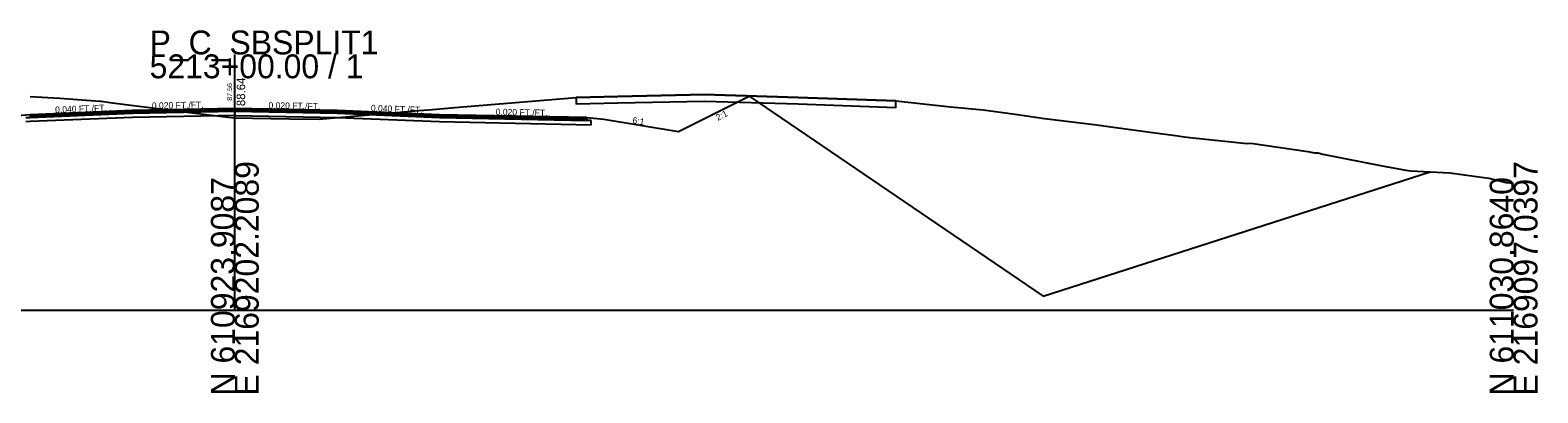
# Model space of a CAD drawing. Extents: x -26 to 1303, y -3010 to 12033.
# Drawn here: x 1126 to 1302.8, y 8490.3 to 8532.8 of the extents above; entities that cross this region are included whole.
import ezdxf

# ---------------------------------------------------------------- set-up
doc = ezdxf.new("R2010")
doc.units = 0
for name, color, linetype in [('RD_GPK_XS_Cell', 7, 'Continuous'), ('RD_Sketch10', 7, 'Continuous'), ('RD_XS_Base', 7, 'Continuous'), ('RD_XS_ExGround', 7, 'Continuous'), ('RD_XS_ExPaveRet', 7, 'Continuous'), ('RD_XS_Greenside', 7, 'Continuous'), ('RD_XS_Pave', 7, 'Continuous'), ('RD_XS_PaveOvlay_CP', 7, 'Continuous'), ('RD_XS_TieSlope', 7, 'Continuous'), ('RD_XS_TX_Elev_EX', 7, 'Continuous'), ('RD_XS_TX_Elev_PR', 7, 'Continuous'), ('RD_XS_TX_Slope', 7, 'Continuous')]:
    doc.layers.add(name, color=color, linetype=linetype)

msp = doc.modelspace()

# ---------------------------------------------------------------- linework, layer by layer
at = {"layer": 'RD_GPK_XS_Cell'}
for p, q in [((1150, 8500), (1150, 8530)), ((1000, 8500), (1150, 8500)), ((1150, 8500), (1300, 8500))]:
    msp.add_line(p, q, dxfattribs=at)
at = {"layer": 'RD_Sketch10'}
msp.add_lwpolyline([(1210.33, 8525.12), (1244.82, 8501.65), (1290.21, 8516.23)], dxfattribs=at)
at = {"layer": 'RD_XS_Base'}
for p, q in [((1125.5, 8522.59), (1126, 8522.61)), ((1126, 8522.61), (1138, 8523.09)), ((1126, 8522.61), (1126, 8522.61)), ((1138, 8522.59), (1126, 8522.11)), ((1136, 8523.01), (1136, 8523.01)), ((1136, 8522.51), (1136, 8522.51)), ((1138, 8523.09), (1150, 8523.33)), ((1150, 8522.83), (1138, 8522.59)), ((1150, 8523.33), (1150, 8523.49)), ((1150, 8523.49), (1150, 8522.83)), ((1150, 8523.33), (1150, 8522.83)), ((1150, 8523.33), (1150, 8523.33)), ((1162, 8523.09), (1150, 8523.33)), ((1150, 8523.33), (1150, 8523.33)), ((1150, 8522.83), (1150, 8522.83)), ((1150, 8522.83), (1150, 8522.83)), ((1150, 8522.83), (1162, 8522.59)), ((1174, 8522.61), (1162, 8523.09)), ((1162, 8523.09), (1162, 8523.09)), ((1162, 8522.59), (1162, 8522.59)), ((1162, 8522.59), (1174, 8522.11)), ((1191.3, 8522.26), (1174, 8522.61)), ((1174, 8522.61), (1174, 8522.61)), ((1126, 8522.11), (1125.5, 8522.09)), ((1126, 8522.11), (1126, 8522.11)), ((1174, 8522.11), (1174, 8522.11)), ((1174, 8522.11), (1191.8, 8521.75)), ((1191.8, 8522.25), (1191.3, 8522.26)), ((1191.3, 8522.26), (1191.3, 8522.26)), ((1191.8, 8521.75), (1191.8, 8522.25)), ((1191.8, 8522.25), (1191.8, 8522.25)), ((1191.8, 8521.75), (1191.8, 8521.75)), ((1191.8, 8521.75), (1191.8, 8521.75))]:
    msp.add_line(p, q, dxfattribs=at)
at = {"layer": 'RD_XS_ExGround'}
msp.add_lwpolyline([(1125.98, 8525.08), (1129.46, 8524.85), (1134.18, 8524.51), (1134.35, 8524.5), (1135.35, 8524.37), (1142.15, 8523.5), (1148.23, 8522.75), (1149.87, 8522.55), (1156.42, 8522.46), (1159.89, 8522.4), (1164.4, 8522.81), (1171.59, 8523.4), (1172.74, 8523.5), (1175.81, 8523.76), (1190.03, 8524.96), (1194.91, 8525.07), (1205.07, 8525.28), (1216.08, 8524.94), (1227.52, 8524.54), (1233.95, 8523.83), (1237.79, 8523.49), (1241.53, 8522.98), (1244.98, 8522.49), (1251.09, 8521.73), (1252.75, 8521.5), (1257.95, 8520.81), (1260.35, 8520.5), (1261.38, 8520.33), (1262.02, 8520.24), (1268.76, 8519.56), (1269.19, 8519.57), (1275.86, 8518.6), (1276.66, 8518.47), (1277.06, 8518.44), (1277.62, 8518.29), (1284.76, 8516.91), (1287.57, 8516.37), (1287.92, 8516.35), (1292.51, 8516.1), (1297.11, 8515.5), (1299.07, 8514.96), (1300, 8514.89)], dxfattribs=at)
at = {"layer": 'RD_XS_ExPaveRet'}
for points in [[(1216.08, 8524.94), (1205.07, 8525.28), (1205.07, 8525.28), (1205.07, 8525.28), (1194.91, 8525.07), (1194.91, 8525.07), (1190.03, 8524.96), (1190.03, 8524.21), (1190.03, 8524.21), (1194.91, 8524.32), (1194.91, 8524.32), (1205.07, 8524.53), (1205.07, 8524.53), (1205.07, 8524.53), (1216.08, 8524.19), (1216.08, 8524.19), (1227.52, 8523.79), (1227.52, 8523.79), (1227.52, 8524.54), (1216.08, 8524.94), (1216.08, 8524.94)], [(1216.08, 8524.94), (1205.07, 8525.28), (1194.91, 8525.07), (1190.03, 8524.96), (1190.03, 8524.21), (1194.91, 8524.32), (1205.07, 8524.53), (1216.08, 8524.19), (1227.52, 8523.79), (1227.52, 8524.54), (1216.08, 8524.94)]]:
    msp.add_lwpolyline(points, dxfattribs=at)
at = {"layer": 'RD_XS_Greenside'}
for p, q in [((1202.03, 8520.96), (1210.33, 8525.12)), ((1193.3, 8522.42), (1202.03, 8520.96))]:
    msp.add_line(p, q, dxfattribs=at)
at = {"layer": 'RD_XS_Pave'}
for p, q in [((1138, 8523.4), (1126, 8522.92)), ((1138, 8523.24), (1126, 8522.77)), ((1126, 8522.77), (1138, 8523.24)), ((1126, 8522.61), (1138, 8523.09)), ((1126, 8522.92), (1126, 8522.92)), ((1126, 8522.92), (1126, 8522.77)), ((1126, 8522.77), (1126, 8522.77)), ((1126, 8522.77), (1126, 8522.61)), ((1126, 8522.77), (1126, 8522.77)), ((1126, 8522.77), (1126, 8522.77)), ((1126, 8522.61), (1126, 8522.61)), ((1126, 8522.61), (1126, 8522.61)), ((1136, 8523.32), (1136, 8523.32)), ((1136, 8523.16), (1136, 8523.16)), ((1136, 8523.16), (1136, 8523.16)), ((1136, 8523.01), (1136, 8523.01)), ((1150, 8523.64), (1138, 8523.4)), ((1150, 8523.49), (1138, 8523.24)), ((1138, 8523.24), (1150, 8523.49)), ((1138, 8523.09), (1150, 8523.33)), ((1162, 8523.4), (1150, 8523.64)), ((1150, 8523.33), (1150, 8523.49)), ((1150, 8523.49), (1162, 8523.24)), ((1162, 8523.24), (1150, 8523.49)), ((1150, 8523.49), (1150, 8523.49)), ((1150, 8523.49), (1150, 8523.33)), ((1150, 8523.33), (1150, 8523.33)), ((1150, 8523.33), (1150, 8523.33)), ((1150, 8523.33), (1150, 8523.33)), ((1150, 8523.33), (1162, 8523.09)), ((1174, 8522.92), (1162, 8523.4)), ((1162, 8523.4), (1162, 8523.4)), ((1162, 8523.24), (1162, 8523.24)), ((1162, 8523.24), (1174, 8522.77)), ((1174, 8522.77), (1162, 8523.24)), ((1162, 8523.24), (1162, 8523.24)), ((1162, 8523.09), (1162, 8523.09)), ((1162, 8523.09), (1174, 8522.61)), ((1191.3, 8522.58), (1174, 8522.92)), ((1174, 8522.92), (1174, 8522.92)), ((1174, 8522.77), (1174, 8522.77)), ((1174, 8522.77), (1191.3, 8522.42)), ((1191.3, 8522.42), (1174, 8522.77)), ((1174, 8522.77), (1174, 8522.77)), ((1174, 8522.61), (1174, 8522.61)), ((1174, 8522.61), (1191.3, 8522.26)), ((1191.3, 8522.42), (1191.3, 8522.58)), ((1191.3, 8522.58), (1191.3, 8522.58)), ((1191.3, 8522.42), (1191.3, 8522.42)), ((1191.3, 8522.42), (1191.3, 8522.42)), ((1191.3, 8522.26), (1191.3, 8522.42)), ((1191.3, 8522.42), (1191.3, 8522.42)), ((1191.3, 8522.26), (1191.3, 8522.26)), ((1191.3, 8522.26), (1191.3, 8522.26))]:
    msp.add_line(p, q, dxfattribs=at)
at = {"layer": 'RD_XS_PaveOvlay_CP'}
for p, q in [((1138, 8523.4), (1126, 8522.92)), ((1126, 8522.92), (1126, 8522.92)), ((1136, 8523.32), (1136, 8523.32)), ((1150, 8523.64), (1138, 8523.4)), ((1162, 8523.4), (1150, 8523.64)), ((1174, 8522.92), (1162, 8523.4)), ((1162, 8523.4), (1162, 8523.4)), ((1191.3, 8522.58), (1174, 8522.92)), ((1174, 8522.92), (1174, 8522.92)), ((1191.3, 8522.58), (1191.3, 8522.58))]:
    msp.add_line(p, q, dxfattribs=at)
at = {"layer": 'RD_XS_TieSlope'}
for p, q in [((1126, 8522.92), (1120, 8522.44)), ((1191.3, 8522.58), (1193.3, 8522.42))]:
    msp.add_line(p, q, dxfattribs=at)

# ---------------------------------------------------------------- texts
at = {"layer": 'RD_GPK_XS_Cell'}
for s, p in [('P_C_SBSPLIT1', (1140, 8530)), ('5213+00.00 / 1', (1140, 8527.2))]:
    msp.add_text(s, height=2.8, dxfattribs=at).set_placement(p)
for s, p in [('E 2169202.2089', (1152.8, 8490)), ('E 2169097.0397', (1302.8, 8490)), ('N 610923.9087', (1150, 8490)), ('N 611030.8640', (1300, 8490))]:
    msp.add_text(s, height=2.8, rotation=90, dxfattribs=at).set_placement(p)
at = {"layer": 'RD_XS_TX_Elev_EX'}
msp.add_text('87.56', height=0.6, rotation=90, dxfattribs=at).set_placement((1149.67, 8524.56))
at = {"layer": 'RD_XS_TX_Elev_PR'}
msp.add_text('88.64', height=1, rotation=90, dxfattribs=at).set_placement((1151.21, 8523.93))
at = {"layer": 'RD_XS_TX_Slope'}
for s, rotation, p in [('0.020 FT./FT.', 1.1458, (1140.27, 8523.61)), ('0.020 FT./FT.', 358.8542, (1153.94, 8523.66)), ('0.040 FT./FT.', 2.2906, (1128.93, 8523.13)), ('0.040 FT./FT.', 357.7094, (1165.94, 8523.34)), ('0.020 FT./FT.', 358.8542, (1180.59, 8522.89)), ('6:1', 350.5377, (1196.6, 8521.93)), ('2:1', 26.5651, (1206.65, 8522.19))]:
    msp.add_text(s, height=0.75, rotation=rotation, dxfattribs=at).set_placement(p)

doc.saveas('drawing.dxf')
